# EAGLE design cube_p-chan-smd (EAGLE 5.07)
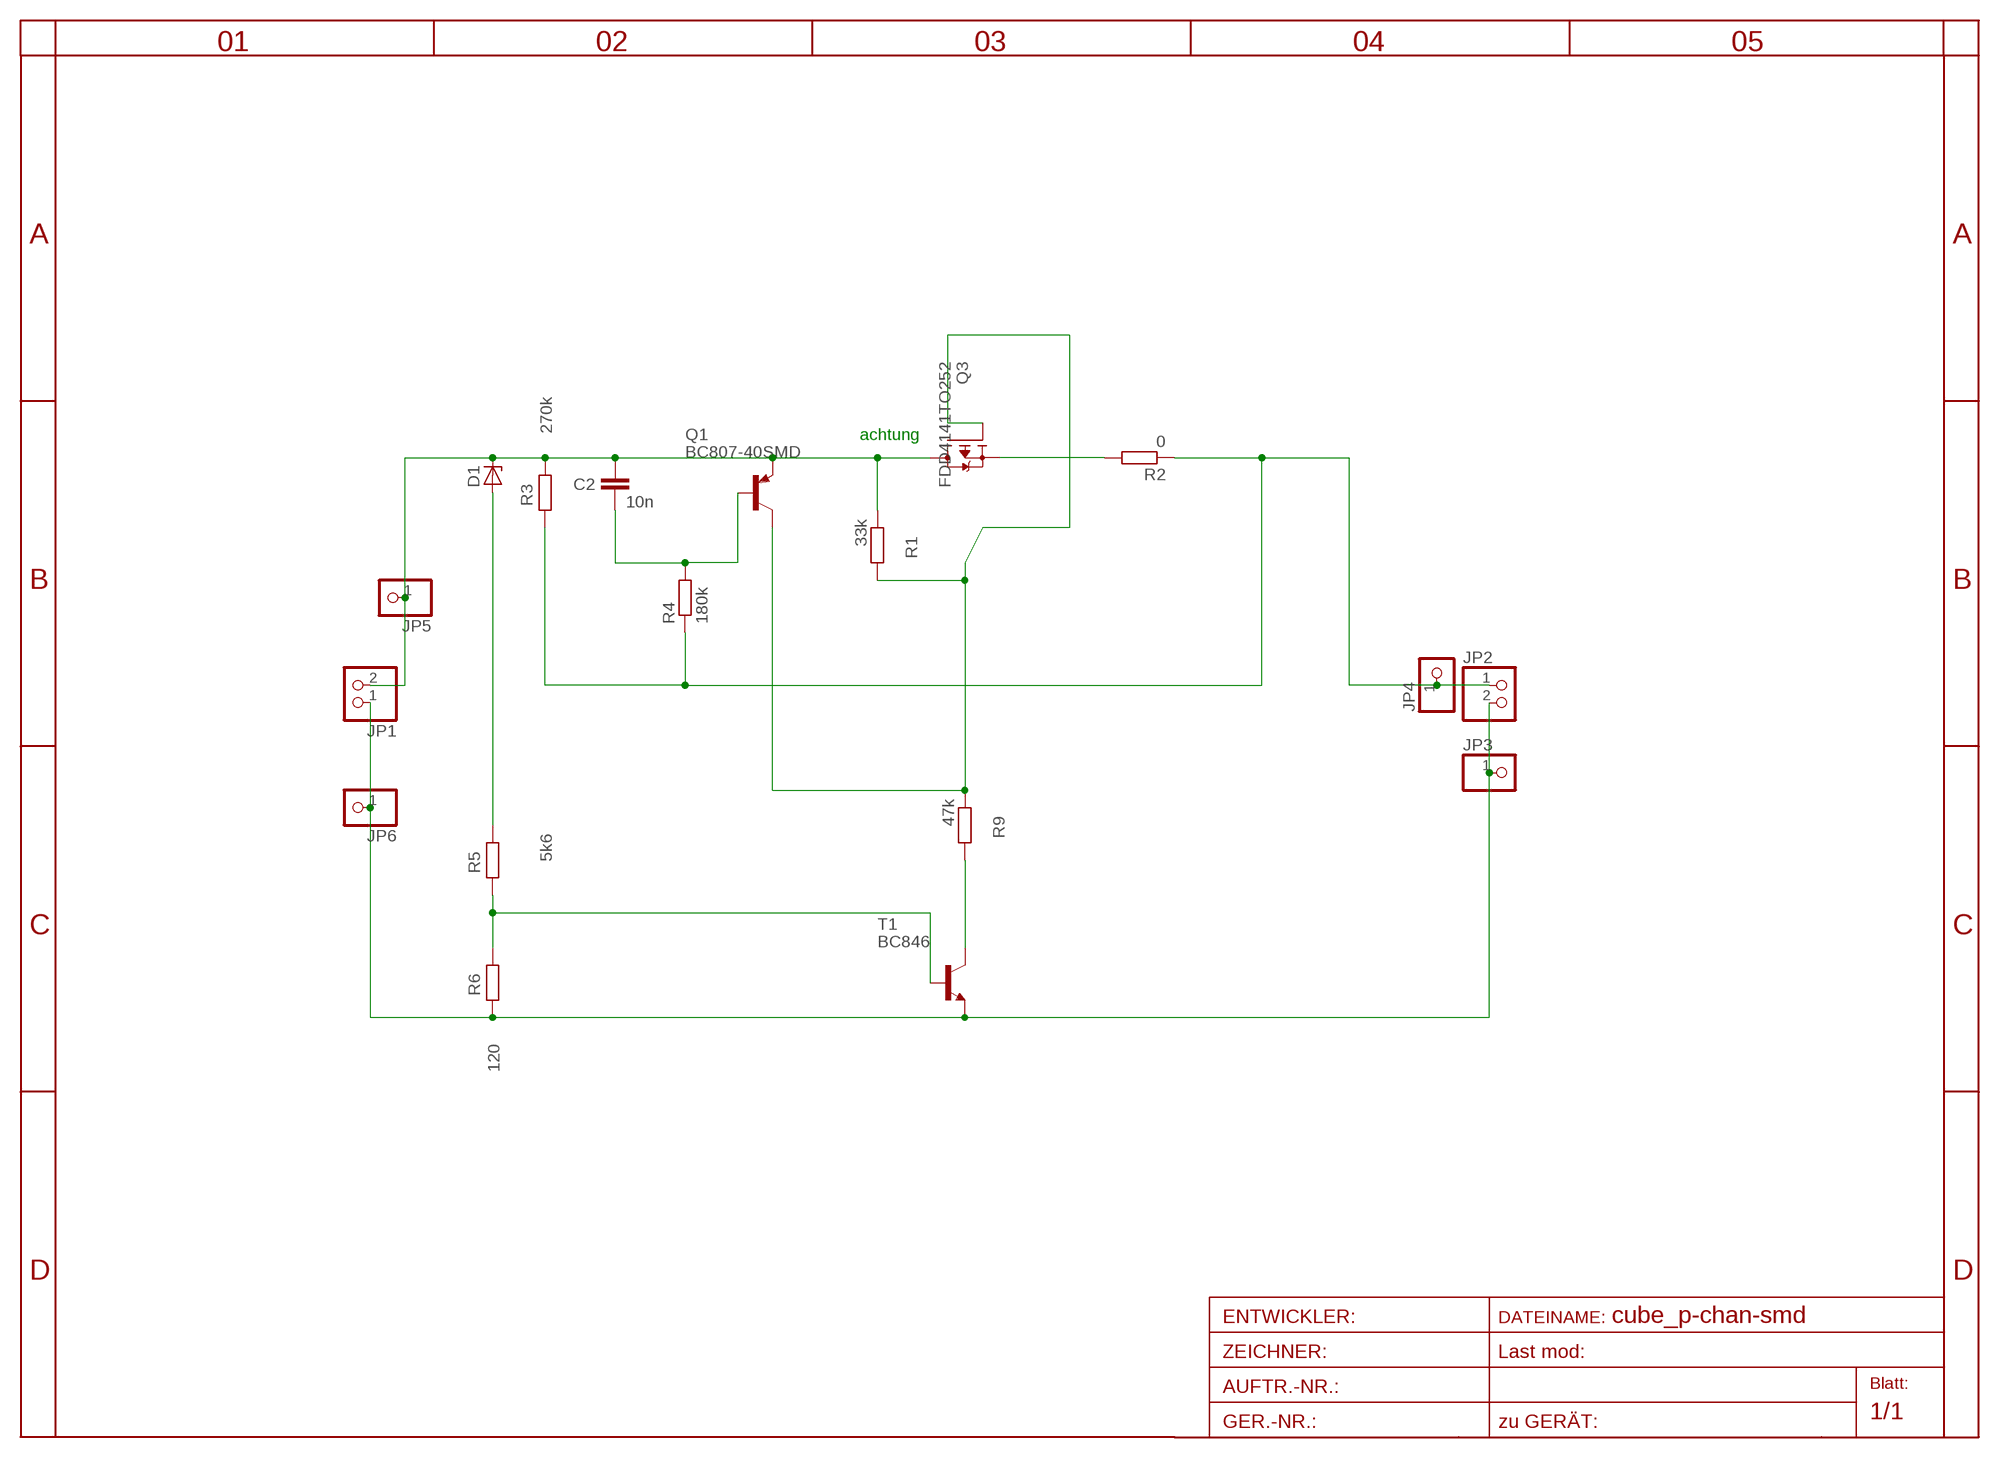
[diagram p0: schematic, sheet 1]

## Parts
C2  10n  C-EUC1206  [C1206]
D1  ZENER-DIODESOD80C  [SOD80C]
JP1  PINHD-1X2  [1X02]
JP2  PINHD-1X2  [1X02]
JP3  PINHD-1X11MM6  [1X1MM8]
JP4  PINHD-1X11MM6  [1X1MM8]
JP5  PINHD-1X11MM6  [1X1MM8]
JP6  PINHD-1X11MM6  [1X1MM8]
Q1  BC807-40SMD  [SOT23-BEC]
Q3  FDD4141TO252  [TO252]
R1  33k  R-EU_R1206  [R1206]
R2  0  R-EU_0204/5  [0204/5]
R3  270k  R-EU_R1206  [R1206]
R4  180k  R-EU_R1206  [R1206]
R5  5k6  R-EU_R1206  [R1206]
R6  120  R-EU_R1206  [R1206]
R9  47k  R-EU_R1206  [R1206]
T1  BC846  [SOT23]

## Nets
B-Q1: C2.2 Q1.B R4.2
D: Q3.3(S) R2.2
GATE: Q1.C Q3.1(G) R1.2 R9.1
N$1: D1.A R5.1
N$2: R9.2 T1.3(C)
N$3: R5.2 R6.1 T1.1(B)
V+IN: C2.1 D1.C JP1.2 JP5.1 Q1.E Q3.2(D) R1.1 R3.1
V+OUT: JP2.1 JP4.1 R2.1 R3.2 R4.1
V-: JP1.1 JP2.2 JP3.1 JP6.1 R6.2 T1.2(E)

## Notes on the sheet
- achtung

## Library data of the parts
C2 = rcl-2:C-EU: CAPACITOR, European symbol
D1 = diode-1:ZENER-DIODE: Z-Diode
JP1 JP2 = pinhead:PINHD-1X2: PIN HEADER
JP3-JP6 = pinhead:PINHD-1X1: PIN HEADER
Q1 = transistor-pnp:BC807*: PNP Transistror
Q3 = transistor-fet:FDD4141: P-Channel PowerTrench® MOSFET Source: FDD4141.pdf
R1-R6 R9 = rcl-2:R-EU_: RESISTOR, European symbol
T1 = transistor:BC846: NPN TRANSISTOR

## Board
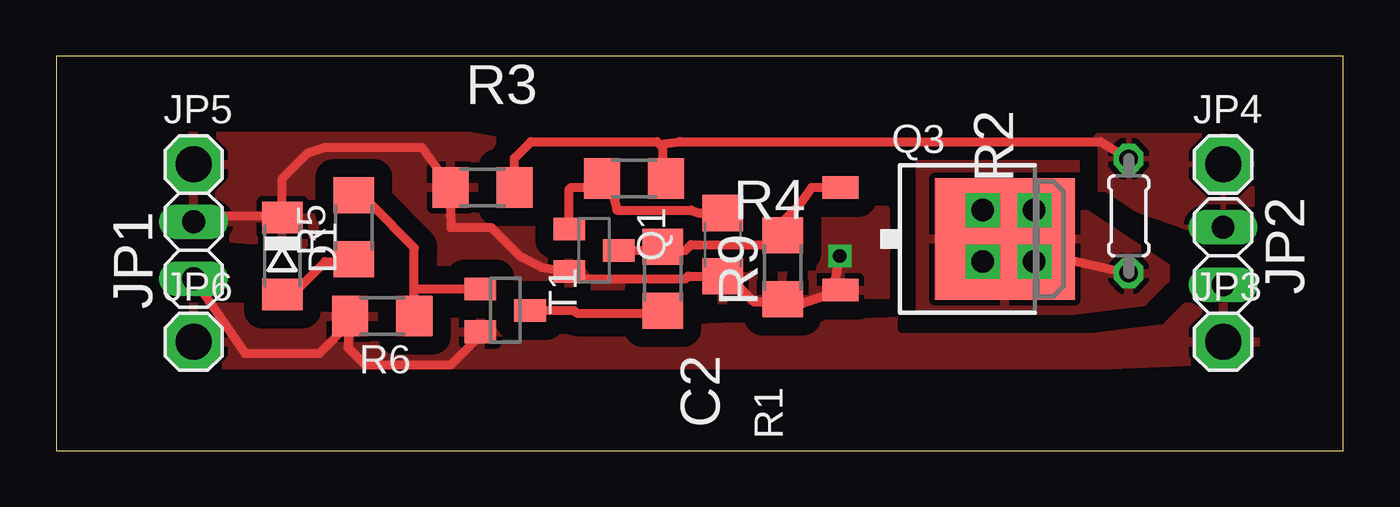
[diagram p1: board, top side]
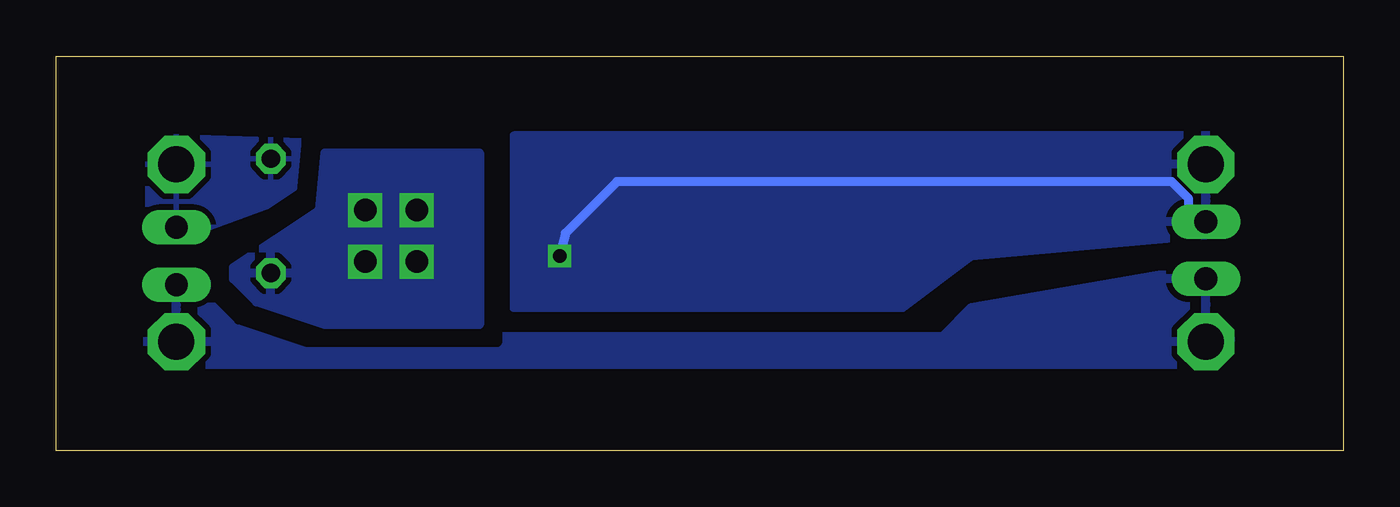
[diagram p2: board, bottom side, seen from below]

Size 57.15 x 17.5 mm. Coordinates in mm from the lower left corner, seen from the top.
Outline: 0,0 57.15,0 57.15,17.5 0,17.5 0,0
Copper layers (1*16): Top 0.035mm / dielectric 1.5mm / Bottom 0.035mm
Design rules "default": minimum track width 10mil, minimum drill 24mil, track to track 8mil, track to pad 8mil, pad to pad 8mil, via to via 8mil, smd to smd 8mil, copper to edge 40mil, drill to drill 8mil, minimum pad ring 10mil, minimum via ring 8mil, stop-mask expansion 4mil, vias tented up to drill 0mil, thermal gap 10mil

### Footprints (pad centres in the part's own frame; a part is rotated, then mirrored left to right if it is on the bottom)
C1206 = smd 1.6 x 1.8: 1 -1.4,0; 2 1.4,0
SOD80C = smd 1.4 x 1.8: A 1.7,0; C -1.7,0
1X02 = drill 1.016 long: 1 -1.27,0; 2 1.27,0
1X1MM8 = drill 1.6 pad 2.54 octagon: 1 0,0
SOT23-BEC = smd 1 x 1.4: B -0.95,-1.1; C 0,1.1; E 0.95,-1.1
TO252 = smd 1 x 1.6: 1 -2.28,-4.8; 2 2.28,-4.8 | smd 5.4 x 6.2: 3 0,2.5
R1206 = smd 1.6 x 1.803: 1 -1.422,0; 2 1.422,0
0204/5 = drill 0.813 octagon: 1 -2.54,0; 2 2.54,0
SOT23 = smd 1 x 1.4: 1 -0.95,-1.1; 2 0.95,-1.1; 3 0,1.1

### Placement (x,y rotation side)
C2  29.59,9.14 90 top
D1  10.03,8.64 270 top
JP1  6.1,8.89 90 top
JP2  51.82,8.64 270 top
JP3  51.82,4.83 0 top
JP4  51.82,12.7 0 top
JP5  6.1,12.7 0 top
JP6  6.1,4.83 0 top
Q1  23.88,8.89 270 top
Q3  39.62,9.4 270 top
R1  32.26,8.13 90 top
R2  47.62,10.41 270 top
R3  18.92,11.68 0 top
R4  25.65,12.07 180 top
R5  13.21,9.91 90 top
R6  14.48,5.97 180 top
R9  26.92,7.62 270 top
T1  19.94,6.22 270 top

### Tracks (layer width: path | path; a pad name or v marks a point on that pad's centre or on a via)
B-Q1
  Top 0.406: Q1.B 22.78,11.6 22.86,11.68 23.84,11.68 R4.2 24.62,11.68 24.64,11.68 24.89,10.67 28.19,10.67 28.58,10.54 C2.2
D  (via drill 1)
  Top 0.406: R2.2 44.2,8.64 43.18,9.65 42.38,9.65 Q3.3
  other vias: 43.43,10.67 41.15,10.67 41.15,8.38 43.43,8.38
  pour Bottom: 38.35,13.21 38.35,5.59 45.21,5.59 48.26,6.6 49.28,7.62 49.28,8.13 45.47,10.67 45.21,13.21
  pour Top (isolate 0.61): 38.35,13.21 38.35,6.22 45.21,6.22 48.26,6.6 49.28,7.62 49.28,8.13 45.47,10.67 45.21,13.21
GATE
  Top 0.406: R9.1 26.77,8.89 Q1.C 27.94,8.89 28.19,9.14 31.85,9.14 R1.2 32.26,10.16 33.02,10.92 33.55,11.68 Q3.1
N$1
  Top 0.406: D1.A 10.49,6.94 11.94,8.38 13.11,8.38 R5.1
N$2
  Top 0.406: T1.3 22.99,6.22 23.11,6.1 26.82,6.1 R9.2
N$3
  Top 0.406: R6.1 15.9,7.11 | 15.9,7.11 15.9,8.99 13.97,10.92 13.61,10.92 R5.2 | T1.1 15.96,7.17 15.9,7.11
V+IN  (via drill 0.6)
  Top 0.406: JP1.2 6.6,10.41 9.96,10.41 D1.C 10.03,12.06 11.18,13.21 11.94,13.46 16.23,13.46 R3.1 17.5,10.44 17.53,9.91 19.3,9.91 20.57,8.64 21.57,8.13 Q1.E 23.1,7.62 27.94,7.62 28.06,7.74 C2.1 29.85,7.74 30.99,6.6 32.16,6.6 R1.1 32.61,6.36 Q3.2 | v34.8,8.64 34.57,7.59
  Bottom 0.406: v34.8,8.64 34.54,9.65 32.26,11.94 7.62,11.94 6.86,11.18 6.86,10.67 JP1.2
  pour Bottom (isolate 0.813, rank 5): 5.33,9.65 5.33,13.97 36.83,13.97 36.83,6.35 19.56,6.35 16.51,8.64
  pour Top (isolate 0.813, rank 5): 5.08,9.65 5.08,13.97 18.29,13.97 36.83,10.67 36.83,6.35 19.56,6.35 16.51,8.64
V+OUT
  Top 0.406: R3.2 20.34,12.98 21.08,13.72 26.67,13.72 26.8,13.59 | 26.8,13.59 26.92,13.46 26.92,12.22 R4.1 | R2.1 46.35,13.72 27.69,13.72 26.8,13.59
  pour Bottom (isolate 0.813, rank 5): 44.96,13.21 44.7,13.72 53.09,13.97 53.09,8.89 45.47,11.68
  pour Top (isolate 0.813, rank 5): 45.72,13.21 46.23,13.97 53.09,13.97 53.09,8.89 45.97,11.43
V-
  Top 0.406: T1.2 18.84,5.12 17.53,3.81 13.72,3.81 12.95,4.57 12.95,5.87 R6.2 13.06,5.69 11.68,4.32 8.38,4.32 JP1.1
  pour Bottom (isolate 0.813, rank 4): 4.83,8.38 5.08,3.81 53.09,3.81 53.09,8.13 45.47,6.35 41.4,5.08 17.78,5.08 16.51,6.35
  pour Top (isolate 0.813, rank 4): 5.08,6.35 5.08,3.81 44.45,3.81 50.8,4.83 50.8,6.6 45.47,6.35 40.89,5.84 17.78,5.08 16.51,6.35
  pour Top (isolate 0.813, rank 4): 7.37,6.35 7.37,3.81 46.74,3.81 53.34,4.06 53.09,6.6 47.5,5.59 43.18,5.84 20.07,5.08 18.8,6.35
